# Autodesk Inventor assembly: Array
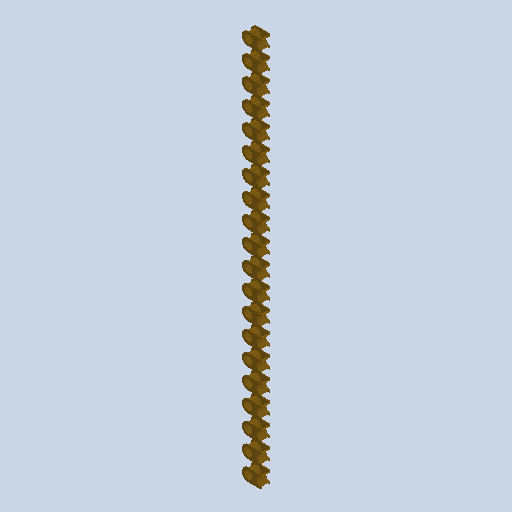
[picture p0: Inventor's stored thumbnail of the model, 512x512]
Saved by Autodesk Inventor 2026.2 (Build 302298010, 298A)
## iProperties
Created: 2026-10
Part Number: Array
Document SubType Name: Assembly
Designer: mel
Author: mel
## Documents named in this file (2)
- D:\travail\année 2026-2027\1 sti2d IT\poubelle à verre\raspberry-pico-2-microcontroller-rp2350-1.snapshot.5\raspberry_pico_2\raspberry_pico_2\Array.iam
- D:\travail\année 2026-2027\1 sti2d IT\poubelle à verre\raspberry-pico-2-microcontroller-rp2350-1.snapshot.5\raspberry_pico_2\raspberry_pico_2\castel_hole.ipt
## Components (20 placed, 20 different names)
1. 2598
2. 2599
3. 2600
4. 2601
5. 2602
6. 2603
7. 2604
8. 2605
9. 2606
10. 2607
11. 2608
12. 2609
13. 2610
14. 2611
15. 2612
16. 2613
17. 2614
18. 2615
19. 2616
20. 2617
